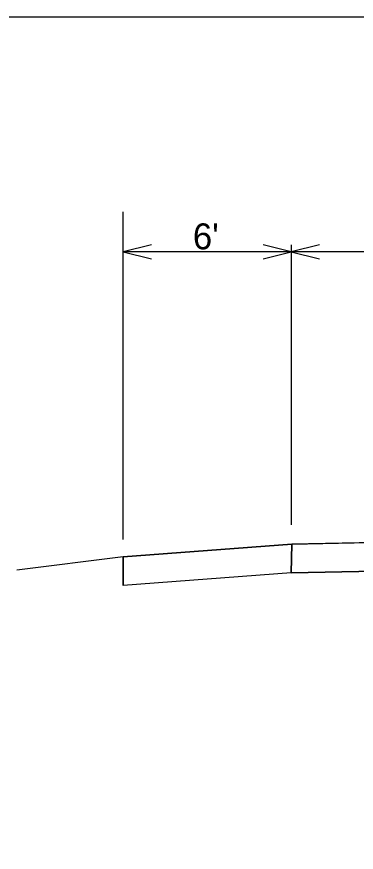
# Model space of a CAD drawing. Extents: x 10133 to 81668, y 4856 to 11018.
# Drawn here: x 11342.4 to 11538.9, y 9460.9 to 9944 of the extents above; entities that cross this region are included whole.
import ezdxf

# ---------------------------------------------------------------- set-up
doc = ezdxf.new("R2010")
doc.units = 0
for name, color, linetype in [('dsnXsPCCPavementBottom', 7, 'Continuous'), ('dsnXsShldrEarthFill', 7, 'Continuous'), ('dsnXsShldrGranular', 7, 'Continuous'), ('dsnXsShldrGranularBottom', 7, 'Continuous'), ('dsnXsShldrSpecialBackBottom', 7, 'Continuous'), ('SheetBorder', 7, 'Continuous')]:
    doc.layers.add(name, color=color, linetype=linetype)

msp = doc.modelspace()

# ---------------------------------------------------------------- linework, layer by layer
at = {"layer": 'dsnXsPCCPavementBottom'}
for p, q in [((11403.92, 9641.68), (11403.92, 9831.28)), ((11501.33, 9812.17), (11501.33, 9650.3)), ((11501.33, 9808.07), (11403.92, 9808.07)), ((11700.24, 9808.07), (11501.57, 9808.07))]:
    msp.add_line(p, q, dxfattribs=at)
for points in [[(11420.31, 9812.17), (11403.92, 9808.07), (11420.31, 9803.97)], [(11484.94, 9803.97), (11501.33, 9808.07), (11484.94, 9812.17)], [(11517.72, 9812.17), (11501.33, 9808.07), (11517.72, 9803.97)]]:
    msp.add_lwpolyline(points, dxfattribs=at)
at = {"layer": 'dsnXsShldrGranular'}
msp.add_line((11700.35, 9626.7), (11501.33, 9622.47), dxfattribs=at)
msp.add_lwpolyline([(11501.33, 9622.47), (11501.57, 9639.03), (11700, 9643.25)], dxfattribs=at)
msp.add_lwpolyline([(11403.92, 9631.76), (11501.57, 9639.03), (11501.33, 9622.47), (11403.92, 9615.16)], close=True, dxfattribs=at)
at = {"layer": 'dsnXsShldrGranularBottom'}
for p, q in [((11700, 9643.25), (11501.57, 9639.03)), ((11501.57, 9639.03), (11501.33, 9622.47)), ((11403.92, 9631.76), (11342.37, 9624.03)), ((11501.33, 9622.47), (11700.35, 9626.7))]:
    msp.add_line(p, q, dxfattribs=at)
at = {"layer": 'dsnXsShldrSpecialBackBottom'}
for p, q in [((11501.57, 9639.03), (11403.92, 9631.76)), ((11403.92, 9631.76), (11403.92, 9615.16)), ((11501.33, 9622.41), (11403.92, 9615.16))]:
    msp.add_line(p, q, dxfattribs=at)
at = {"layer": 'SheetBorder'}
msp.add_lwpolyline([(10132.52, 9944.02), (13267.53, 9944.02), (13267.53, 7924.02), (10132.52, 7924.02)], close=True, dxfattribs=at)

# ---------------------------------------------------------------- texts
at = {"layer": 'dsnXsShldrEarthFill'}
msp.add_text("6'", height=15, rotation=360, dxfattribs=at).set_placement((11444.35, 9809.53))

doc.saveas('drawing.dxf')
